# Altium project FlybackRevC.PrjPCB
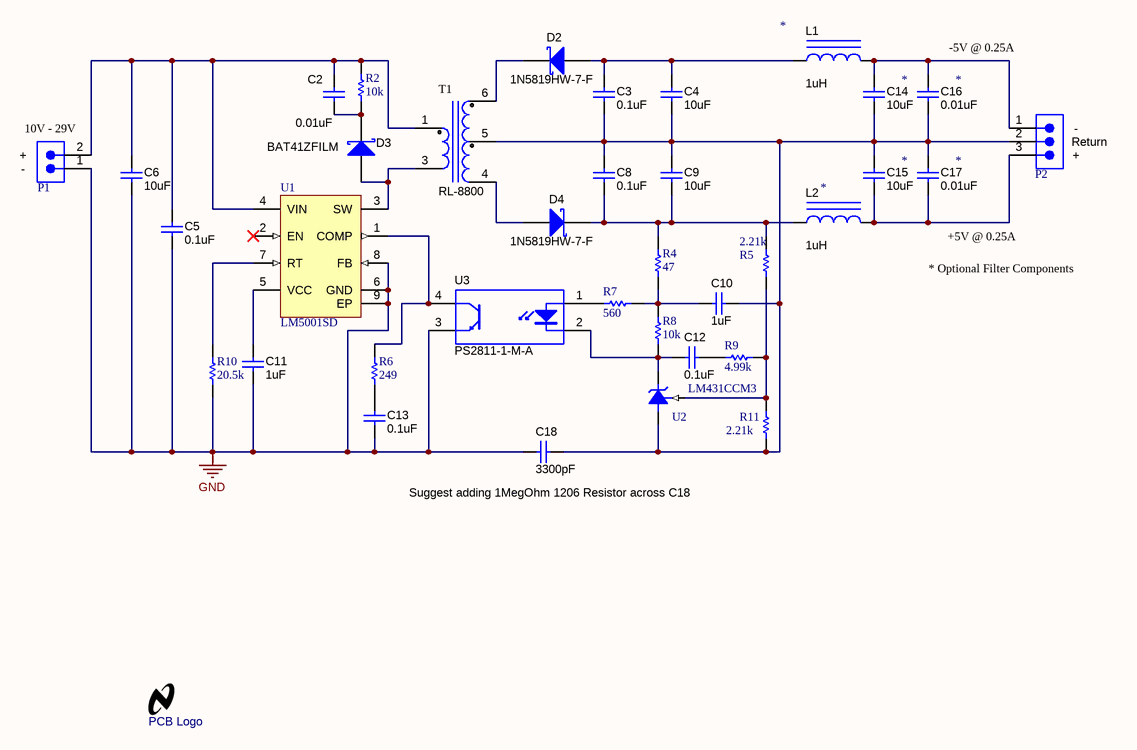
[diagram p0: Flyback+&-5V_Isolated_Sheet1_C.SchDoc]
PRJ_BasePN: 600154; PRJ_Customer: Public Release; PRJ_Title: Analog Split Rail; SCH_Rev: C
1 sheet, 37 parts. Net scope: global (net labels, ports and power ports of the same name join across sheets).
Board file: Split Rail RevC.PcbDoc

## Sheet Flyback+&-5V_Isolated_Sheet1_C.SchDoc: LM5001
size Letter; Author: R. H.; Organization: National Semiconductor; Address1: 2900 Semiconductor Dr.; Address3: Santa Clara, CA  95051; Address4: United States; Revision: XP-1; SheetNumber: 1; SheetTotal: 1; TechSupport: http://www.national.com/support/; PageSetup: Record=PageOptions|CenterHorizontal=True|CenterVertical=True|PrintScale=0.94|XCorrection=1.00|YCorrection=1.00|PrintKind=0|BorderSize=5000000|LeftOffset=0|BottomOffset=0|Orientation=2|PaperLength=1000|PaperWidth=1000|Scale=100|PaperSource=7|PrintQuality=-4|MediaType=1|DitherType=10|PaperKind=Letter 8.5 x 11in|PrintScaleMode=1

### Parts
C2  value 0.01uF  [0603]  (hidden comment: GRM188R71H103KA01D)
C3  value 0.1uF  [0402]  (hidden comment: C1005X5R1A104K)
C4  value 10uF  [0805_HV]  (hidden comment: EMK212BJ106KG-T)
C5  value 0.1uF  [0603]  (hidden comment: GRM188R71H104KA93D)
C6  value 10uF  [1210]  (hidden comment: ECJ-4YF1H106Z)
C8  value 0.1uF  [0402]  (hidden comment: C1005X5R1A104K)
C9  value 10uF  [0805_HV]  (hidden comment: EMK212BJ106KG-T)
C10  value 1uF  [0603]  (hidden comment: C1608Y5V1A105Z)
C11  value 1uF  [0603]  (hidden comment: C1608Y5V1A105Z)
C12  value 0.1uF  [0402]  (hidden comment: C1005X5R1A104K)
C13  value 0.1uF  [0402]  (hidden comment: C1005X5R1A104K)
C14  value 10uF  [0805_HV]  (hidden comment: EMK212BJ106KG-T)
C15  value 10uF  [0805_HV]  (hidden comment: EMK212BJ106KG-T)
C16  value 0.01uF  [0402]  (hidden comment: C1005X7R1C103K)
C17  value 0.01uF  [0402]  (hidden comment: C1005X7R1C103K)
C18  value 3300pF  [1206]  (hidden comment: C3216C0G2J332J)
D2  1N5819HW-7-F  [SOD-123]
D3  BAT41ZFILM  [SOD-123]
D4  1N5819HW-7-F  [SOD-123]
L1  value 1uH  [ME3220]  (hidden comment: ME3220-102MLB)
L2  value 1uH  [ME3220]  (hidden comment: ME3220-102MLB)
Logo?  PCB Logo  [Worldmark_CopperSolderMask_Small]  (no BOM)
P1  TSW-102-07-G-S  [TSW-102-07-X-S]  (value not drawn)
P2  TSW-103-07-G-S  [TSW-103-07-X-S]  (value not drawn)
R2  value 10k  [0402]  (hidden comment: CRCW040210K0JNED)
R4  value 47  [0402]  (hidden comment: CRCW040247R0JNED)
R5  value 2.21k  [0402]  (hidden comment: CRCW04022K21FKED)
R6  value 249  [0402]  (hidden comment: CRCW0402249RFKED)
R7  value 560  [0402]  (hidden comment: CRCW0402560RJNED)
R8  value 10k  [0402]  (hidden comment: CRCW040210K0JNED)
R9  value 4.99k  [0402]  (hidden comment: CRCW04024K99FKED)
R10  value 20.5k  [0402]  (hidden comment: CRCW040220K5FKED)
R11  value 2.21k  [0402]  (hidden comment: CRCW04022K21FKED)
T1  RL-8800  [S32890]
U1  LM5001SD  [SDC08A]
U2  LM431CCM3  [MF03A_N]
U3  PS2811-1-M-A  [PS2811-1]

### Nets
GND: C5.2 C6.2 C11.2 C13.2 C18.2 P1.1 R10.1 U1.6(GND) U1.8(FB) U1.9(EP) U3.3(E)
NetC2_1: C2.1 C5.1 C6.1 P1.2 R2.1 T1.1 U1.4(VIN)
NetC2_2: C2.2 D3.2(K) R2.2
NetC3_1: C3.1 C4.2 D2.1(A) L1.1
NetC3_2: C3.2 C4.1 C8.1 C9.1 C10.1 C14.2 C15.1 C16.2 C17.1 C18.1 P2.2 R11.1 T1.5 U2.3(A)
NetC8_2: C8.2 C9.2 D4.2(K) L2.1 R4.2 R5.1
NetC10_2: C10.2 R4.1 R7.1 R8.1
NetC11_1: C11.1 U1.5(VCC)
NetC12_1: C12.1 R8.2 U2.1(K) U3.2(K)
NetC12_2: C12.2 R9.2
NetC13_1: C13.1 R6.2
NetC14_1: C14.1 C16.1 L1.2 P2.1
NetC15_2: C15.2 C17.2 L2.2 P2.3
NetD2_2: D2.2(K) T1.6
NetD3_1: D3.1(A) T1.3 U1.3(SW)
NetD4_1: D4.1(A) T1.4
NetR5_2: R5.2 R9.1 R11.2 U2.2(REF)
NetR6_1: R6.1 U1.1(COMP) U3.4(C)
NetR7_2: R7.2 U3.1(A)
NetR10_2: R10.2 U1.7(RT)

Not connected (* = marked no-connect by the designer): T1 2; U1 2(EN)*

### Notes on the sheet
- (near L1) *
- (near C16) -5V @ 0.25A
- (near P1) 10V - 29V
- *
- (near C16) *
- (near P2) -
- (near P2) Return
- (near P1) +
- (near P1) -
- (near L2) *
- (near C17) *
- (near P2) +
- * Optional Filter Components
- +5V @ 0.25A
- (near C18) Suggest adding 1MegOhm 1206 Resistor across C18

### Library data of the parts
C2 = GRM188R71H103KA01D: CAP, CERM, 0.01uF, 50V, +/-10%, X7R, 0603; Manufacturer: MuRata; CompType: Capacitor; Polarized: N; Cap_F: 10.0E-9; TaMax_C: 125; TaMin_C: -55; Tolerance_%: 10; VDC_V: 50; ValueDisplayed: 0.01µF
C3 C8 = C1005X5R1A104K: CAP, CERM, 0.1uF, 10V, +/-10%, X5R, 0402; Manufacturer: TDK; CompType: Capacitor; Polarized: N; Cap_F: 100.0E-9; ESR_Ohm: 0.0186; TaMax_C: 85; TaMin_C: -55; Tolerance_%: 10; Value1: 0.0186 ohm; ValueDisplayed: 0.1µF
C4 C9 = EMK212BJ106KG-T: CAP, CERM, 10uF, 16V, +/-10%, X5R, 0805; Manufacturer: Taiyo Yuden; Cap_Case: 0805; CompType: Capacitor; Polarized: N; TaMax_C: 85; TaMin_C: -55; Tolerance_%: 10; VDC_V: 16; Cap_F: 10.0E-6; ValueDisplayed: 10µF
C5 = GRM188R71H104KA93D: CAP, CERM, 0.1uF, 50V, +/-10%, X7R, 0603; Manufacturer: MuRata; CompType: Capacitor; Polarized: N; Cap_F: 100.0E-9; TaMax_C: 125; TaMin_C: -55; Tolerance_%: 10; VDC_V: 50; ValueDisplayed: 0.1µF
C6 = Capacitor: Cap, Ceramic  Y5V, -20/+80%, 1210; Manufacturer: Panasonic; Polarized: N; Cap_F: 10E-06; Tolerance_%: -20 +80; VDC_V: 50V
C10 = C1608Y5V1A105Z: CAP, CERM, 1uF, 10V, +80/-20%, Y5V, 0603; Manufacturer: TDK; CompType: Capacitor; Polarized: N; Cap_F: 1.0E-6; ESR_Ohm: 0.01; TaMax_C: 85; TaMin_C: -30; Tolerance_%: 80; Value1: 0.01 ohm; VDC_V: 10; ValueDisplayed: 1µF
C11 = C1608Y5V1A105Z: CAP, CERM, 1uF, 10V, +80/-20%, Y5V, 0603; Manufacturer: TDK; CompType: Capacitor; Polarized: N; ESR_Ohm: 0.01; TaMax_C: 85; TaMin_C: -30; Tolerance_%: 80; VDC_V: 10; Cap_F: 1.0E-6; Value1: 0.01 ohm; ValueDisplayed: 1µF
C12 C13 = C1005X5R1A104K: CAP, CERM, 0.1uF, 10V, +/-10%, X5R, 0402; Manufacturer: TDK; Polarized: N; CompType: Capacitor; Value1: 0.0186 ohm; Cap_F: 100.0E-9; ESR_Ohm: 0.0186; TaMax_C: 85; TaMin_C: -55; Tolerance_%: 10; ValueDisplayed: 0.1µF
C14 C15 = EMK212BJ106KG-T: CAP, CERM, 10uF, 16V, +/-10%, X5R, 0805; Manufacturer: Taiyo Yuden; Cap_Case: 0805; Polarized: N; CompType: Capacitor; Cap_F: 10.0E-6; TaMax_C: 85; TaMin_C: -55; Tolerance_%: 10; VDC_V: 16; ValueDisplayed: 10µF
C16 C17 = C1005X7R1C103K: CAP, CERM, 0.01uF, 16V, +/-10%, X7R, 0402; Manufacturer: TDK; Polarized: N; CompType: Capacitor; Value1: 0.0623 ohm; Cap_F: 10.0E-9; ESR_Ohm: 0.0623; TaMax_C: 125; TaMin_C: -55; Tolerance_%: 10; VDC_V: 16; ValueDisplayed: 0.01µF
C18 = C3216C0G2J332J: CAP, CERM, 3300pF, 630V, +/-5%, C0G/NP0, 1206; Manufacturer: TDK; Polarized: N; CompType: Capacitor; Value1: 0.0369 ohm; Cap_F: 3.3E-9; ESR_Ohm: 0.0369; TaMax_C: 125; TaMin_C: -55; Tolerance_%: 5; VDC_V: 630
D2 D4 = 1N5819HW-7-F: Diode, Schottky, 40V, 1A, SOD-123; Manufacturer: Diodes Inc.; Value: 0.45V; Vf_V: 0.45; Io_A: 1; Vr_V: 40; TJMax_C: 125
D3 = BAT41ZFILM: Diode, Schottky, 100V, 0.2A, SOD-123; Manufacturer: ST Microelectronics; Value: 1V; Vf_V: 1; Io_A: 0.2; Vr_V: 100; TJMax_C: 150
L1 L2 = ME3220-102MLB: Inductor, Drum Core, Ferrite, 1uH, 2.6A, 0.058 ohm, SMD; Manufacturer: Coilcraft; DCR_Ohm: 0.058; Imax_A: 2.6; Ind_H: 1.0E-6; Irms: 2.6A @ 40C rise; Isat: 3.2A @ 30% inductance drop; ValueDisplayed: 1µH
Logo? = NSC Logo: National Semiconductor logo or worldmark; SymbolCreator: codlsc
P1 = TSW-102-07-G-S: Header, TH, 100mil, 1x2, Gold plated, 230 mil above insulator; Manufacturer: Samtec Inc.
P2 = TSW-103-07-G-S: Header, TH, 100mil, 1x3, Gold plated, 230 mil above insulator; Manufacturer: Samtec Inc.
R2 R8 = CRCW040210k0JNED: RES, 10k ohm, 5%, 0.063W, 0402; Manufacturer: Vishay-Dale; CompType: Resistor; Value_Code: 10k0; EIA_Code: E24; Power_W: 0.063; Res_Ohm: 10000; Tolerance_%: 5; VDC_V: 50
R4 = CRCW040247R0JNED: RES, 47 ohm, 5%, 0.063W, 0402; Manufacturer: Vishay-Dale; CompType: Resistor; Value_Code: 47R0; EIA_Code: E24; Power_W: 0.063; Tolerance_%: 5; VDC_V: 50
R5 R11 = CRCW04022k21FKED: RES, 2.21k ohm, 1%, 0.063W, 0402; Manufacturer: Vishay-Dale; CompType: Resistor; Value_Code: 2k21; EIA_Code: E96; Power_W: 0.063; Res_Ohm: 2210; Tolerance_%: 1; VDC_V: 50
R6 = CRCW0402249RFKED: RES, 249 ohm, 1%, 0.063W, 0402; Manufacturer: Vishay-Dale; CompType: Resistor; Value_Code: 249R; EIA_Code: E96; Power_W: 0.063; Tolerance_%: 1; VDC_V: 50
R7 = CRCW0402560RJNED: RES, 560 ohm, 5%, 0.063W, 0402; Manufacturer: Vishay-Dale; CompType: Resistor; Value_Code: 560R; EIA_Code: E24; Power_W: 0.063; Tolerance_%: 5; VDC_V: 50
R9 = CRCW04024k99FKED: RES, 4.99k ohm, 1%, 0.063W, 0402; Manufacturer: Vishay-Dale; CompType: Resistor; Value_Code: 4k99; EIA_Code: E96; Power_W: 0.063; Res_Ohm: 4990; Tolerance_%: 1; VDC_V: 50
R10 = CRCW040220k5FKED: RES, 20.5k ohm, 1%, 0.063W, 0402; Manufacturer: Vishay-Dale; CompType: Resistor; Value_Code: 20k5; EIA_Code: E96; Power_W: 0.063; Res_Ohm: 20500; Tolerance_%: 1; VDC_V: 50
T1 = RL-8800: Flyback Transfomer +5V/-5V @ 2.5W; Manufacturer: Renco Electronics, INC.; Ns2toNp: 0.54:1; CompType: Transformer; LeakageL: 1uH; Lp: 26uH; Rp: 0.21; Rs1: 0.19; SymbolCreator: codlsc
U1 = LM5001SD: High Voltage Switch Mode Regulator; Manufacturer: National Semiconductor; CompType: Switcher; PackageTopMarking: NS*UZXYTT*LM5001
U2 = LM431CCM3: Adjustable Precision Zener Shunt Regulator; Manufacturer: National Semiconductor; CompType: MiscPower; PackageTopMarking: N1B*XTT; PowerWise: N
U3 = PS2811-1-M-A: Low Input Current, Hight CTR Photocoupler; Manufacturer: NEC; CompType: OPTOCOUPLER; SymbolCreator: codlsc

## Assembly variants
Assembled: not fitted C1 C7 R1 R3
